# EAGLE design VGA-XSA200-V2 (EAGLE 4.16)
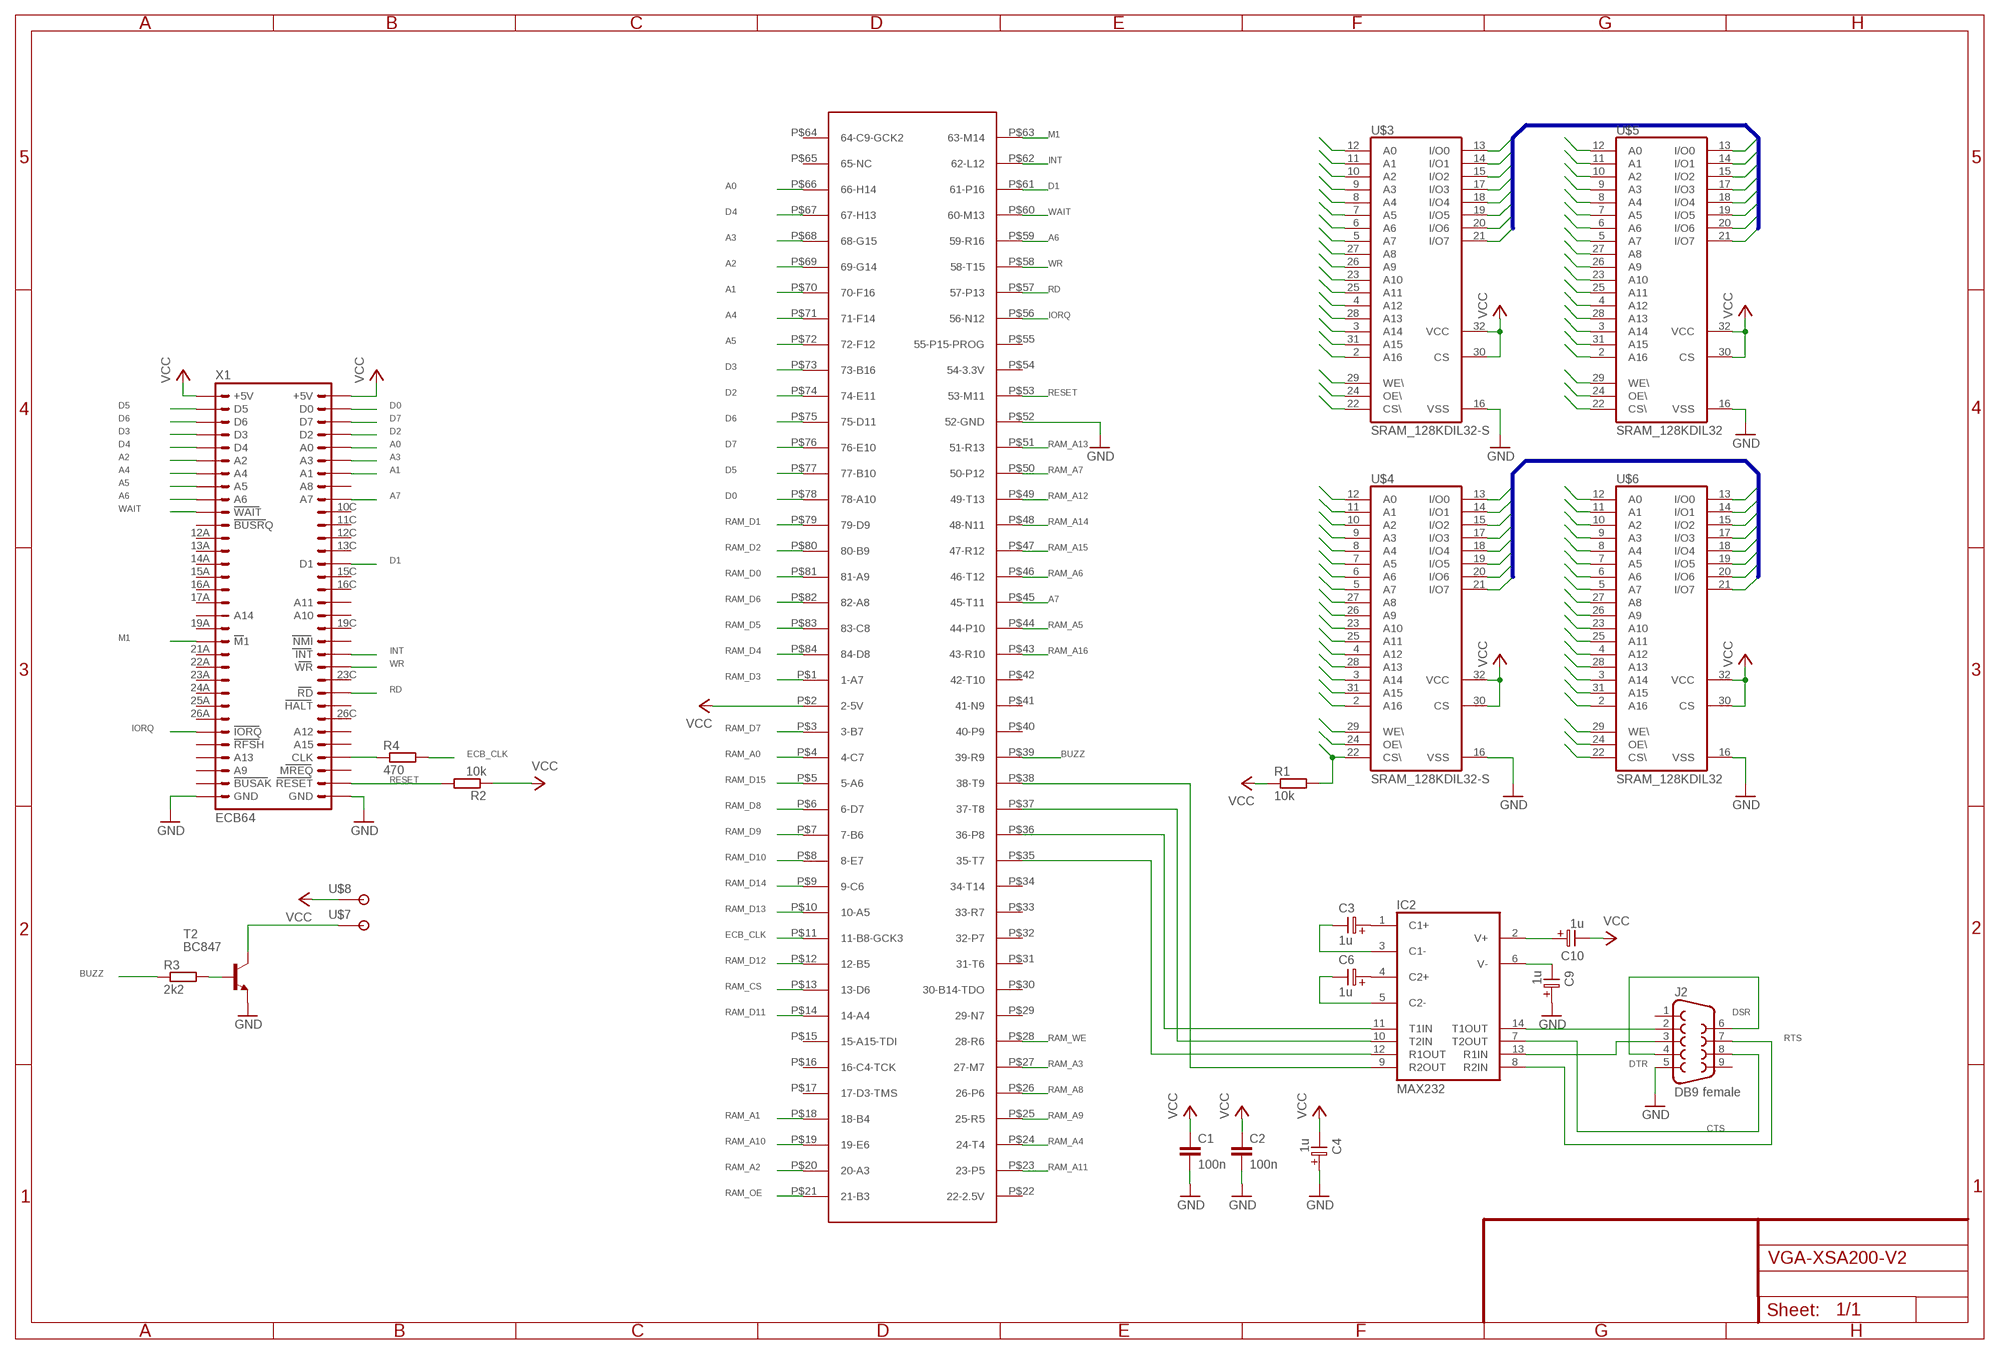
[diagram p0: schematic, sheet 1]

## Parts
C1  100n  C-EU025-025X050  [C025-025X050]
C2  100n  C-EU025-025X050  [C025-025X050]
C3  1u  ELC-2,5L  [ES-2,5L]
C4  1u  ELC-2,5L  [ES-2,5L]
C6  1u  ELC-2,5L  [ES-2,5L]
C9  1u  ELC-2,5L  [ES-2,5L]
C10  1u  ELC-2,5L  [ES-2,5L]
IC2  MAX232  [DIL16]
J2  DB9 female  F09H  [F09H]
R1  10k  R-EU_M1206  [M1206]
R2  10k  R-EU_M1206  [M1206]
R3  2k2  R-EU_M1206  [M1206]
R4  470  R-EU_0204/7  [0204/7]
T2  BC847  BC847-NPN-SOT23-BEC  [SOT23-BEC]
U$1  XSA-200  [XSA-200]
U$3  SRAM_128KDIL32-S  [DIL32-2.PAC]
U$4  SRAM_128KDIL32-S  [DIL32-2.PAC]
U$5  SRAM_128KDIL32  [DIL32]
U$6  SRAM_128KDIL32  [DIL32]
U$7  SPAREPAD10L  [PAD_10_LONG]
U$8  SPAREPAD10L  [PAD_10_LONG]
X1  ECB64  [ML64ECB]

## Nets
A0: U$1.P$66(66-H14) X1.A0
A1: U$1.P$70(70-F16) X1.A1
A2: U$1.P$69(69-G14) X1.A2
A3: U$1.P$68(68-G15) X1.A3
A4: U$1.P$71(71-F14) X1.A4
A5: U$1.P$72(72-F12) X1.A5
A6: U$1.P$59(59-R16) X1.A6
A7: U$1.P$45(45-T11) X1.A7
BUZZ: R3.1 U$1.P$39(39-R9)
CTS: IC2.7(T2OUT) J2.8
D0: U$1.P$78(78-A10) X1.D0
D1: U$1.P$61(61-P16) X1.D1
D2: U$1.P$74(74-E11) X1.D2
D3: U$1.P$73(73-B16) X1.D3
D4: U$1.P$67(67-H13) X1.D4
D5: U$1.P$77(77-B10) X1.D5
D6: U$1.P$75(75-D11) X1.D6
D7: U$1.P$76(76-E10) X1.D7
ECB_CLK: R4.2 U$1.P$11(11-B8-GCK3)
GND: C1.2 C2.2 C4.1 C9.1 J2.5 T2.E U$1.P$52(52-GND) U$3.16(VSS) U$4.16(VSS) U$5.16(VSS) U$6.16(VSS) X1.GND X1.GND@1(GND)
INT: U$1.P$62(62-L12) X1.INT
IORQ: U$1.P$56(56-N12) X1.IORQ
M1: U$1.P$63(63-M14) X1.M1
N$1: IC2.11(T1IN) U$1.P$36(36-P8)
N$2: IC2.12(R1OUT) U$1.P$35(35-T7)
N$3: C3.1 IC2.1(C1+)
N$4: IC2.10(T2IN) U$1.P$37(37-T8)
N$5: C6.1 IC2.4(C2+)
N$6: C3.2 IC2.3(C1-)
N$7: C6.2 IC2.5(C2-)
N$8: IC2.9(R2OUT) U$1.P$38(38-T9)
N$9: T2.C U$7.P$1
N$10: C9.2 IC2.6(V-)
N$11: R3.2 T2.B
N$12: R4.1 X1.CLK
N$13: C10.1 IC2.2(V+)
N$24: J2.4 J2.6
RAM_A0: U$1.P$4(4-C7) U$3.12(A0) U$4.12(A0) U$5.12(A0) U$6.12(A0)
RAM_A1: U$1.P$18(18-B4) U$3.11(A1) U$4.11(A1) U$5.11(A1) U$6.11(A1)
RAM_A2: U$1.P$20(20-A3) U$3.10(A2) U$4.10(A2) U$5.10(A2) U$6.10(A2)
RAM_A3: U$1.P$27(27-M7) U$3.9(A3) U$4.9(A3) U$5.9(A3) U$6.9(A3)
RAM_A4: U$1.P$24(24-T4) U$3.8(A4) U$4.8(A4) U$5.8(A4) U$6.8(A4)
RAM_A5: U$1.P$44(44-P10) U$3.7(A5) U$4.7(A5) U$5.7(A5) U$6.7(A5)
RAM_A6: U$1.P$46(46-T12) U$3.6(A6) U$4.6(A6) U$5.6(A6) U$6.6(A6)
RAM_A7: U$1.P$50(50-P12) U$3.5(A7) U$4.5(A7) U$5.5(A7) U$6.5(A7)
RAM_A8: U$1.P$26(26-P6) U$3.27(A8) U$4.27(A8) U$5.27(A8) U$6.27(A8)
RAM_A9: U$1.P$25(25-R5) U$3.26(A9) U$4.26(A9) U$5.26(A9) U$6.26(A9)
RAM_A10: U$1.P$19(19-E6) U$3.23(A10) U$4.23(A10) U$5.23(A10) U$6.23(A10)
RAM_A11: U$1.P$23(23-P5) U$3.25(A11) U$4.25(A11) U$5.25(A11) U$6.25(A11)
RAM_A12: U$1.P$49(49-T13) U$3.4(A12) U$4.4(A12) U$5.4(A12) U$6.4(A12)
RAM_A13: U$1.P$51(51-R13) U$3.28(A13) U$4.28(A13) U$5.28(A13) U$6.28(A13)
RAM_A14: U$1.P$48(48-N11) U$3.3(A14) U$4.3(A14) U$5.3(A14) U$6.3(A14)
RAM_A15: U$1.P$47(47-R12) U$3.31(A15) U$4.31(A15) U$5.31(A15) U$6.31(A15)
RAM_A16: U$1.P$43(43-R10) U$3.2(A16) U$4.2(A16) U$5.2(A16) U$6.2(A16)
RAM_CS: R1.2 U$1.P$13(13-D6) U$3.22(CS\) U$4.22(CS\) U$5.22(CS\) U$6.22(CS\)
RAM_D0: U$1.P$81(81-A9) U$4.13(I/O0) U$6.13(I/O0)
RAM_D1: U$1.P$79(79-D9) U$4.14(I/O1) U$6.14(I/O1)
RAM_D2: U$1.P$80(80-B9) U$4.15(I/O2) U$6.15(I/O2)
RAM_D3: U$1.P$1(1-A7) U$4.17(I/O3) U$6.17(I/O3)
RAM_D4: U$1.P$84(84-D8) U$4.18(I/O4) U$6.18(I/O4)
RAM_D5: U$1.P$83(83-C8) U$4.19(I/O5) U$6.19(I/O5)
RAM_D6: U$1.P$82(82-A8) U$4.20(I/O6) U$6.20(I/O6)
RAM_D7: U$1.P$3(3-B7) U$4.21(I/O7) U$6.21(I/O7)
RAM_D8: U$1.P$6(6-D7) U$3.13(I/O0) U$5.13(I/O0)
RAM_D9: U$1.P$7(7-B6) U$3.14(I/O1) U$5.14(I/O1)
RAM_D10: U$1.P$8(8-E7) U$3.15(I/O2) U$5.15(I/O2)
RAM_D11: U$1.P$14(14-A4) U$3.17(I/O3) U$5.17(I/O3)
RAM_D12: U$1.P$12(12-B5) U$3.18(I/O4) U$5.18(I/O4)
RAM_D13: U$1.P$10(10-A5) U$3.19(I/O5) U$5.19(I/O5)
RAM_D14: U$1.P$9(9-C6) U$3.20(I/O6) U$5.20(I/O6)
RAM_D15: U$1.P$5(5-A6) U$3.21(I/O7) U$5.21(I/O7)
RAM_OE: U$1.P$21(21-B3) U$3.24(OE\) U$4.24(OE\) U$5.24(OE\) U$6.24(OE\)
RAM_WE: U$1.P$28(28-R6) U$3.29(WE\) U$4.29(WE\) U$5.29(WE\) U$6.29(WE\)
RD: U$1.P$57(57-P13) X1.RD
RESET: R2.2 U$1.P$53(53-M11) X1.RESET
RTS: IC2.8(R2IN) J2.7
RXD: IC2.13(R1IN) J2.3
TXD: IC2.14(T1OUT) J2.2
VCC: C1.1 C2.1 C4.2 C10.2 R1.1 R2.1 U$1.P$2(2-5V) U$3.30(CS) U$3.32(VCC) U$4.30(CS) U$4.32(VCC) U$5.30(CS) U$5.32(VCC) U$6.30(CS) U$6.32(VCC) U$8.P$1 X1.+5V X1.+5V@1(+5V)
WAIT: U$1.P$60(60-M13) X1.WAIT
WR: U$1.P$58(58-T15) X1.WR
Unconnected: J2.1 J2.9 U$1.P$15(15-A15-TDI) U$1.P$16(16-C4-TCK) U$1.P$17(17-D3-TMS) U$1.P$22(22-2.5V) U$1.P$29(29-N7) U$1.P$30(30-B14-TDO) U$1.P$31(31-T6) U$1.P$32(32-P7) U$1.P$33(33-R7) U$1.P$34(34-T14) U$1.P$40(40-P9) U$1.P$41(41-N9) U$1.P$42(42-T10) U$1.P$54(54-3.3V) U$1.P$55(55-P15-PROG) U$1.P$64(64-C9-GCK2) U$1.P$65(65-NC) X1.10C X1.11C X1.12A X1.12C X1.13A X1.13C X1.14A X1.15A X1.15C X1.16A X1.16C X1.17A X1.19A X1.19C X1.21A X1.22A X1.23A X1.23C X1.24A X1.25A X1.26A X1.26C X1.A8 X1.A9 X1.A10 X1.A11 X1.A12 X1.A13 X1.A14 X1.A15 X1.BUSAK X1.BUSRQ X1.HALT X1.MREQ X1.NMI X1.RFSH

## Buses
B$1
B$2

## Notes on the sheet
- DSR
- DTR

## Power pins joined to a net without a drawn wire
GND: IC2.15(GND)
VCC: IC2.16(VCC)

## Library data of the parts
C1 C2 = rcl:C-EU: CAPACITOR, European symbol
C3 C4 C6 C9 C10 = discrete:ELC-2,5L
IC2 = maxim:MAX232: RS232 TRANSEIVER
J2 = con-subd:F09: SUB-D
R1-R4 = rcl:R-EU_: RESISTOR, European symbol
T2 = transistor:*-NPN-: NPN Transistror
U$1 = xess:XSA-200
U$3-U$6 = AD_SRAM:SRAM_128K
U$7 U$8 = ad:SPAREPAD
X1 = con-vg:ECB64: CONNECTOR male, 64 pins, block, type C, rows AC, grid 5.08 mm

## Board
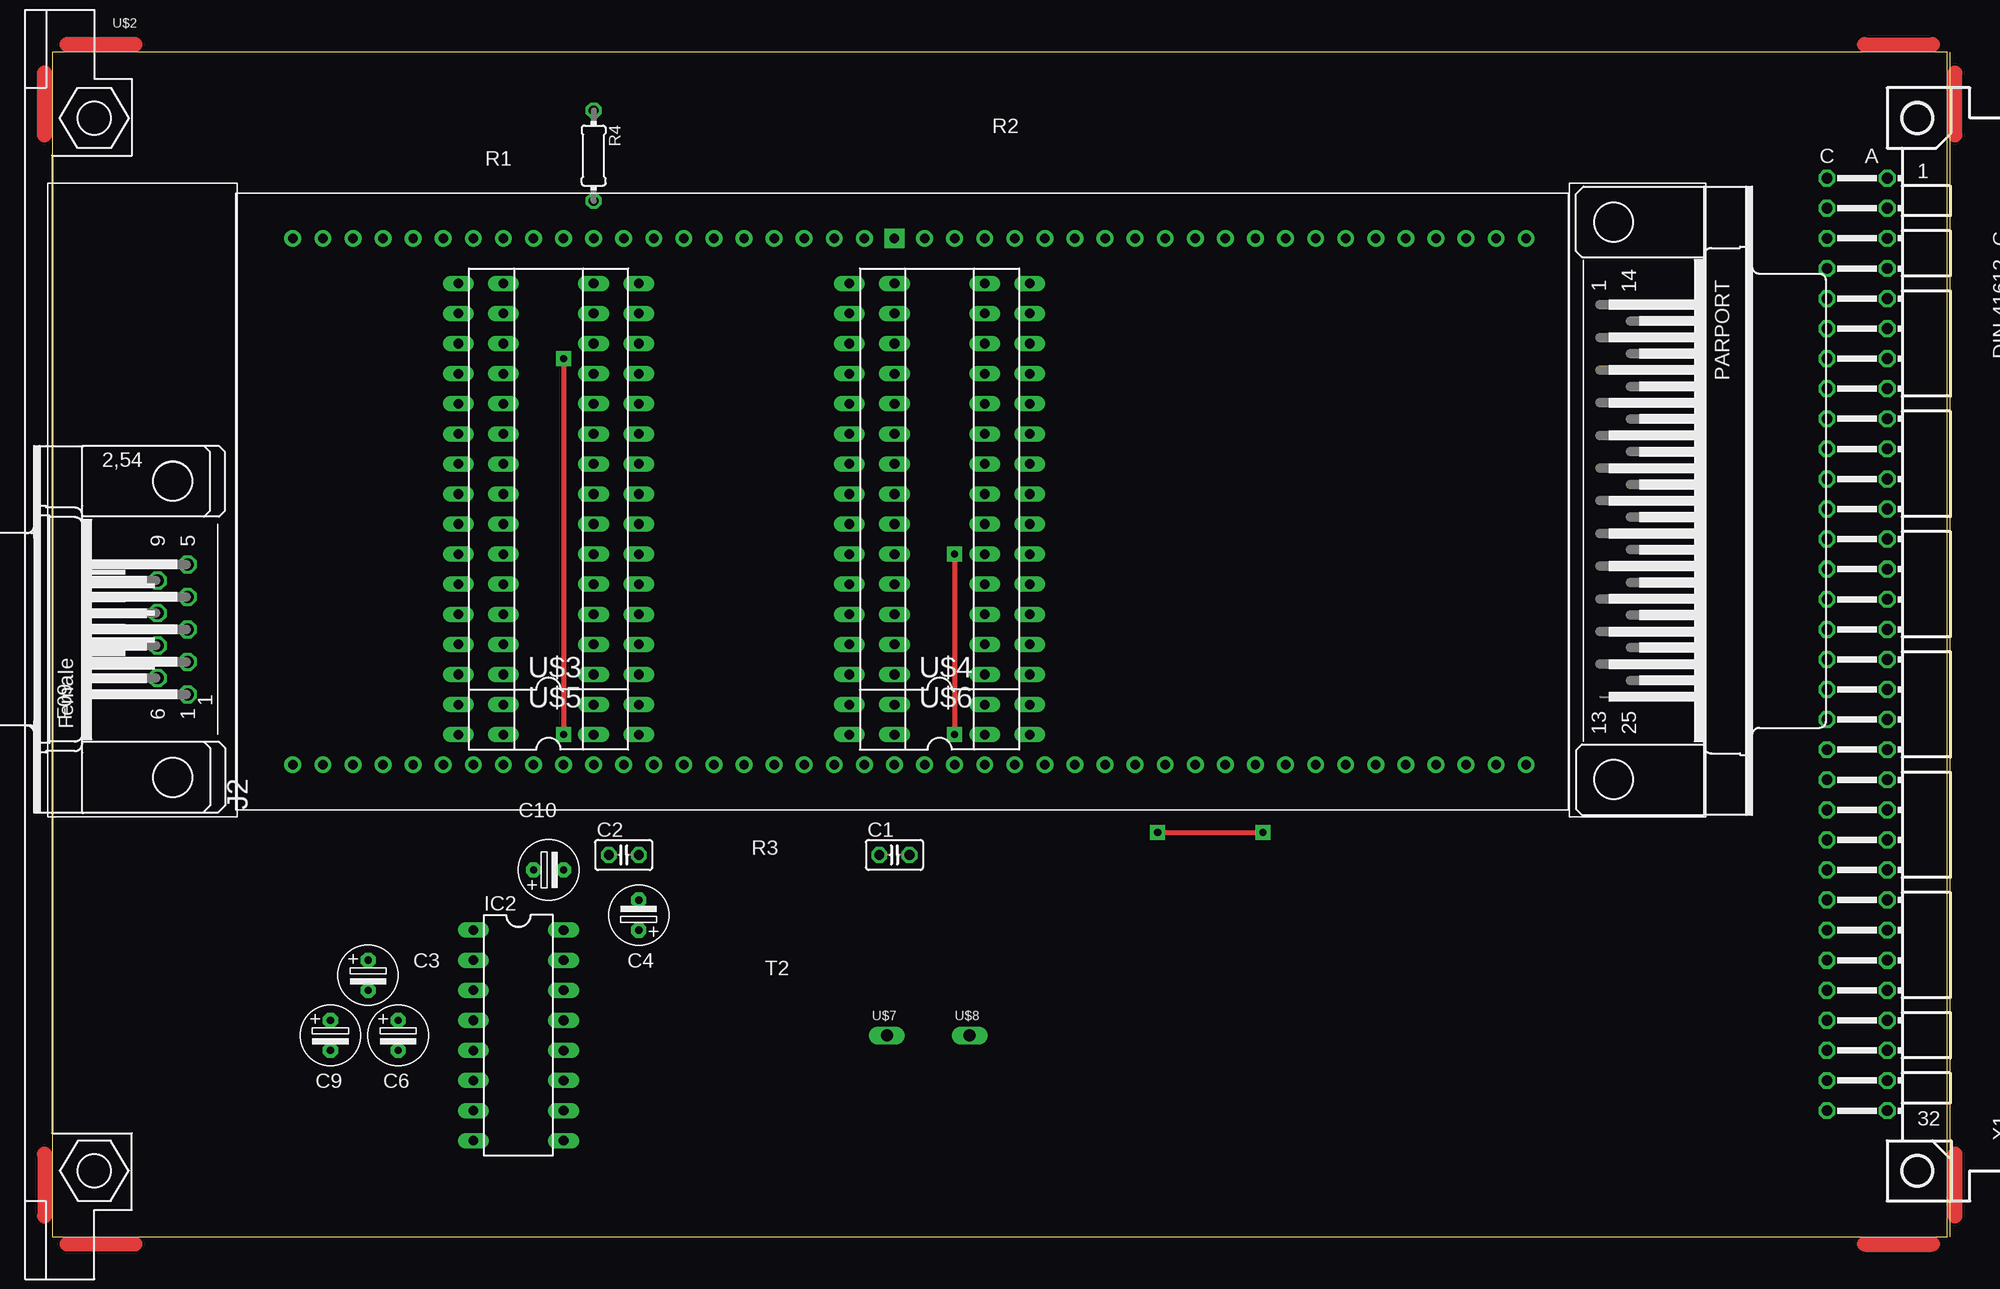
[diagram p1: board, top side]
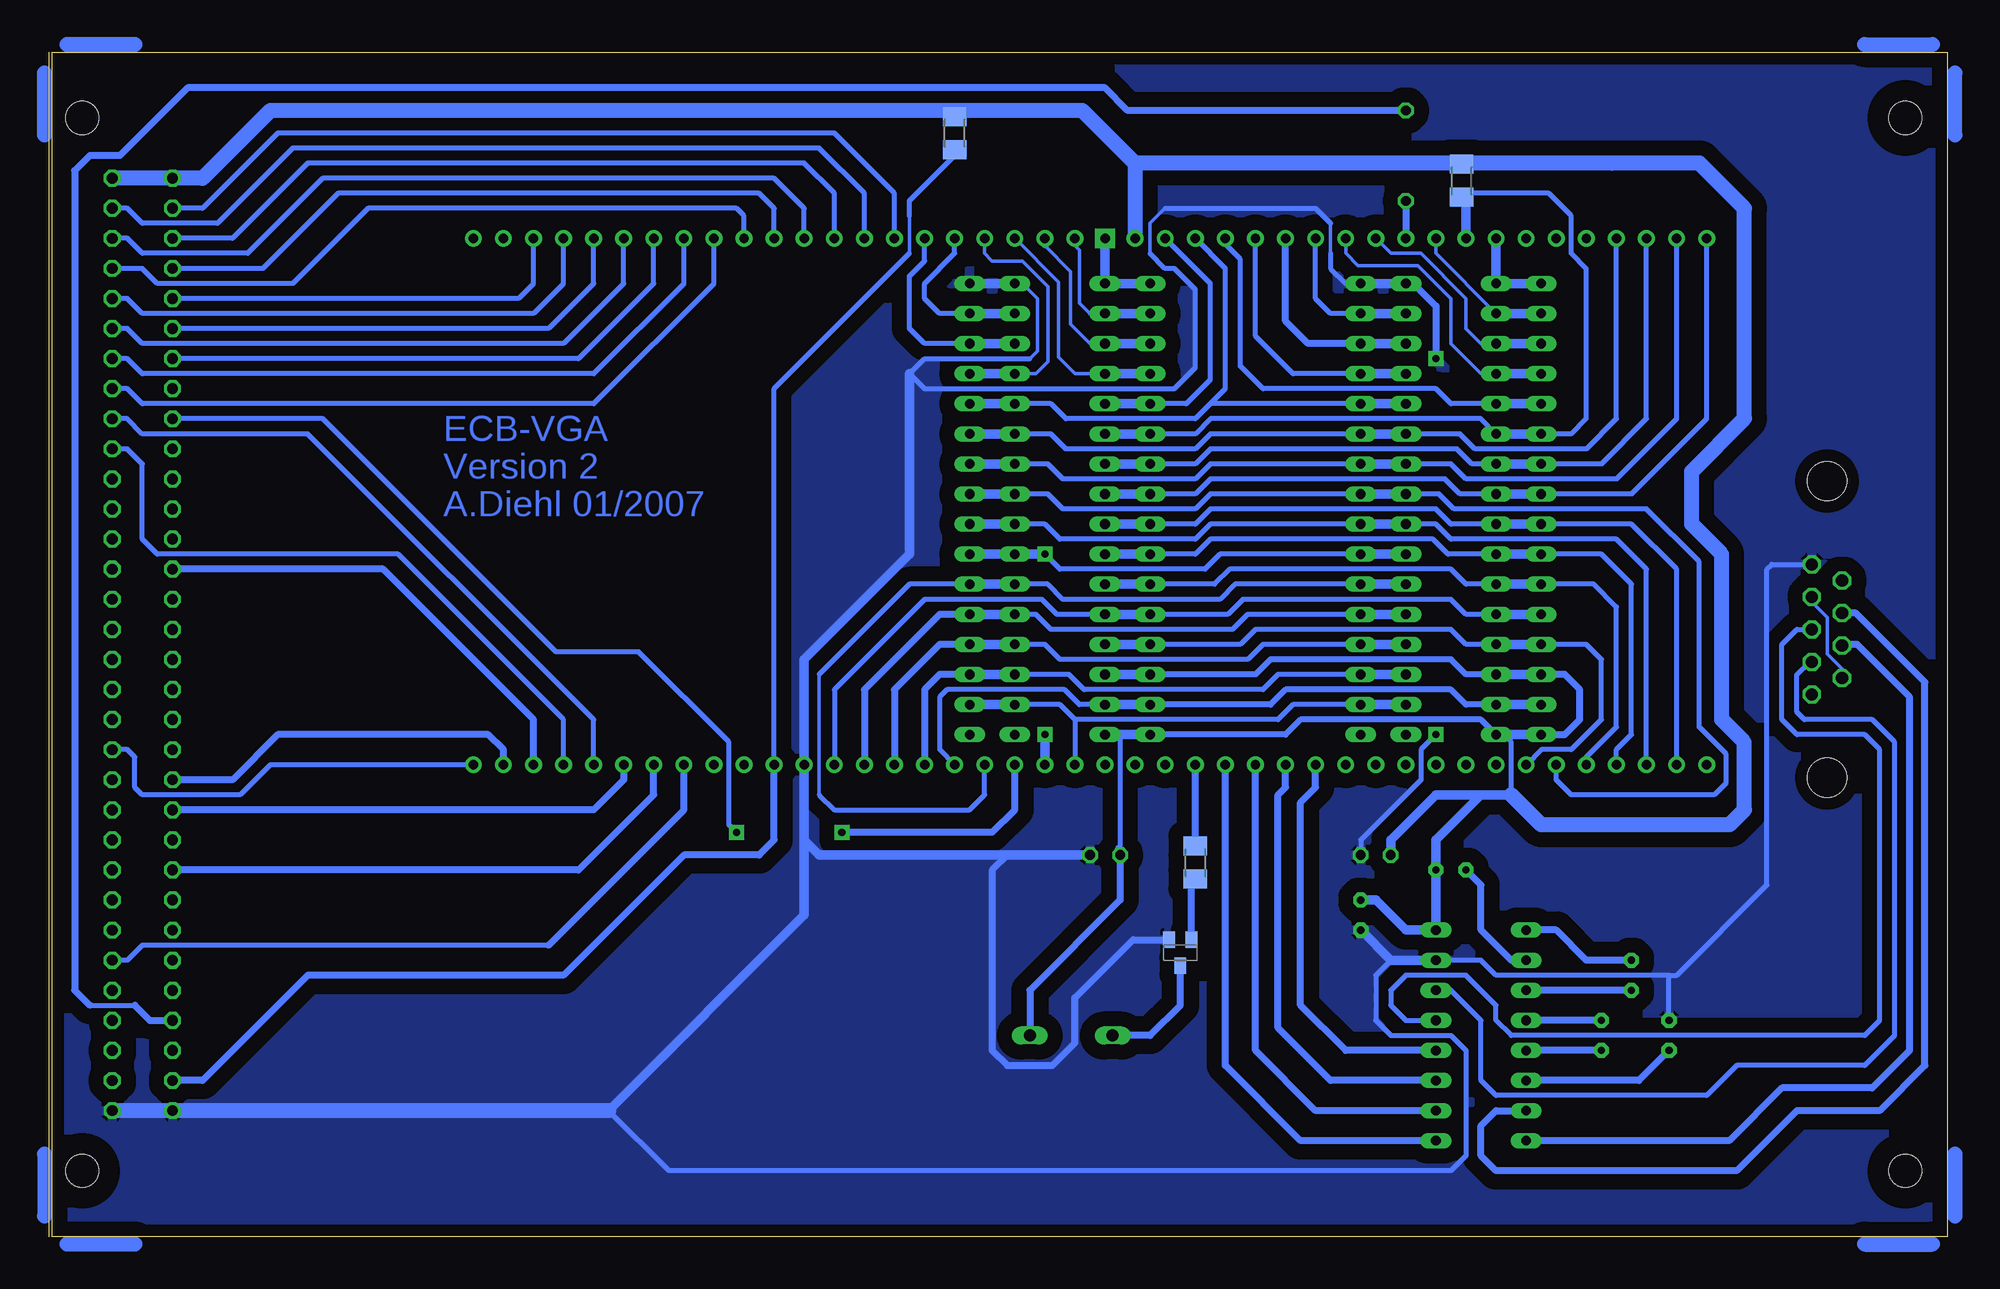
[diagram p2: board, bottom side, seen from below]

Size 160.27 x 100.03 mm. Coordinates in mm from the lower left corner, seen from the top.
Copper layers (1*16): Top 0.035mm / dielectric 1.5mm / Bottom 0.035mm
Design rules "default": minimum track width 10mil, minimum drill 24mil, track to track 50mil, track to pad 60mil, pad to pad 50mil, via to via 50mil, smd to smd 40mil, copper to edge 40mil, drill to drill 8mil, minimum pad ring 10mil, minimum via ring 8mil, stop-mask expansion 4mil, vias tented up to drill 0mil, thermal gap 10mil

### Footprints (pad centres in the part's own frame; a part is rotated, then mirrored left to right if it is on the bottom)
C025-025X050 = drill 0.813 octagon: 1 -1.27,0; 2 1.27,0
ES-2,5L = drill 0.61 pad 1.27 octagon: 1 0,0; 2 2.54,0
DIL16 = drill 0.813 long: 1 -8.89,-3.81; 2 -6.35,-3.81; 3 -3.81,-3.81; 4 -1.27,-3.81; 5 1.27,-3.81; 6 3.81,-3.81; 7 6.35,-3.81; 8 8.89,-3.81; 9 8.89,3.81; 10 6.35,3.81; 11 3.81,3.81; 12 1.27,3.81; 13 -1.27,3.81; 14 -3.81,3.81; 15 -6.35,3.81; 16 -8.89,3.81
F09H = drill 1.016 octagon: 1 -5.486,-1.27; 2 -2.743,-1.27; 3 0,-1.27; 4 2.743,-1.27; 5 5.486,-1.27; 6 -4.115,1.27; 7 -1.372,1.27; 8 1.372,1.27; 9 4.115,1.27 | hole 3.302: -12.522,0; 12.522,0
M1206 = smd 1.6 x 2: 1 -1.4,0; 2 1.4,0
0204/7 = drill 0.813 octagon: 1 -3.81,0; 2 3.81,0
SOT23-BEC = smd 1 x 1.4: B -0.95,-1.1; C 0,1.1; E 0.95,-1.1
XSA-200 = drill 0.8 pad 1.676 square: P$1 -6.35,0 | drill 0.8 pad 1.422 round: P$2 -6.35,-2.54; P$3 -6.35,-5.08; P$4 -6.35,-7.62; P$5 -6.35,-10.16; P$6 -6.35,-12.7; P$7 -6.35,-15.24; P$8 -6.35,-17.78; P$9 -6.35,-20.32; P$10 -6.35,-22.86; P$11 -6.35,-25.4; P$12 -6.35,-27.94; P$13 -6.35,-30.48; P$14 -6.35,-33.02; P$15 -6.35,-35.56; P$16 -6.35,-38.1; P$17 -6.35,-40.64; P$18 -6.35,-43.18; P$19 -6.35,-45.72; P$20 -6.35,-48.26; P$21 -6.35,-50.8; P$22 38.1,-50.8; P$23 38.1,-48.26; P$24 38.1,-45.72; P$25 38.1,-43.18; P$26 38.1,-40.64; P$27 38.1,-38.1; P$28 38.1,-35.56; P$29 38.1,-33.02; P$30 38.1,-30.48; P$31 38.1,-27.94; P$32 38.1,-25.4; P$33 38.1,-22.86; P$34 38.1,-20.32; P$35 38.1,-17.78; P$36 38.1,-15.24; P$37 38.1,-12.7; P$38 38.1,-10.16; P$39 38.1,-7.62; P$40 38.1,-5.08; P$41 38.1,-2.54; P$42 38.1,0; P$43 38.1,2.54; P$44 38.1,5.08; P$45 38.1,7.62; P$46 38.1,10.16; P$47 38.1,12.7; P$48 38.1,15.24; P$49 38.1,17.78; P$50 38.1,20.32; P$51 38.1,22.86; P$52 38.1,25.4; P$53 38.1,27.94; P$54 38.1,30.48; P$55 38.1,33.02; P$56 38.1,35.56; P$57 38.1,38.1; P$58 38.1,40.64; P$59 38.1,43.18; P$60 38.1,45.72; P$61 38.1,48.26; P$62 38.1,50.8; P$63 38.1,53.34; P$64 -6.35,53.34; P$65 -6.35,50.8; P$66 -6.35,48.26; P$67 -6.35,45.72; P$68 -6.35,43.18; P$69 -6.35,40.64; P$70 -6.35,38.1; P$71 -6.35,35.56; P$72 -6.35,33.02; P$73 -6.35,30.48; P$74 -6.35,27.94; P$75 -6.35,25.4; P$76 -6.35,22.86; P$77 -6.35,20.32; P$78 -6.35,17.78; P$79 -6.35,15.24; P$80 -6.35,12.7; P$81 -6.35,10.16; P$82 -6.35,7.62; P$83 -6.35,5.08; P$84 -6.35,2.54
EK-FP = hole 2.794: 3.556,44.45; 3.556,-44.45
DIL32-2.PAC = drill 0.813 long: 1 -19.05,-3.81; 2 -16.51,-3.81; 3 -13.97,-3.81; 4 -11.43,-3.81; 5 -8.89,-3.81; 6 -6.35,-3.81; 7 -3.81,-3.81; 8 -1.27,-3.81; 9 1.27,-3.81; 10 3.81,-3.81; 11 6.35,-3.81; 12 8.89,-3.81; 13 11.43,-3.81; 14 13.97,-3.81; 15 16.51,-3.81; 16 19.05,-3.81; 17 19.05,3.81; 18 16.51,3.81; 19 13.97,3.81; 20 11.43,3.81; 21 8.89,3.81; 22 6.35,3.81; 23 3.81,3.81; 24 1.27,3.81; 25 -1.27,3.81; 26 -3.81,3.81; 27 -6.35,3.81; 28 -8.89,3.81; 29 -11.43,3.81; 30 -13.97,3.81; 31 -16.51,3.81; 32 -19.05,3.81
DIL32 = drill 0.813 long: 1 -19.05,-7.62; 2 -16.51,-7.62; 3 -13.97,-7.62; 4 -11.43,-7.62; 5 -8.89,-7.62; 6 -6.35,-7.62; 7 -3.81,-7.62; 8 -1.27,-7.62; 9 1.27,-7.62; 10 3.81,-7.62; 11 6.35,-7.62; 12 8.89,-7.62; 13 11.43,-7.62; 14 13.97,-7.62; 15 16.51,-7.62; 16 19.05,-7.62; 17 19.05,7.62; 18 16.51,7.62; 19 13.97,7.62; 20 11.43,7.62; 21 8.89,7.62; 22 6.35,7.62; 23 3.81,7.62; 24 1.27,7.62; 25 -1.27,7.62; 26 -3.81,7.62; 27 -6.35,7.62; 28 -8.89,7.62; 29 -11.43,7.62; 30 -13.97,7.62; 31 -16.51,7.62; 32 -19.05,7.62
PAD_10_LONG = drill 1 long: P$1 0,0
ML64ECB = drill 0.914 octagon: 10C -7.62,16.51; 11C -7.62,13.97; 12A -2.54,11.43; 12C -7.62,11.43; 13A -2.54,8.89; 13C -7.62,8.89; 14A -2.54,6.35; 15A -2.54,3.81; 15C -7.62,3.81; 16A -2.54,1.27; 16C -7.62,1.27; 17A -2.54,-1.27; 19A -2.54,-6.35; 19C -7.62,-6.35; 21A -2.54,-11.43; 22A -2.54,-13.97; 23A -2.54,-16.51; 23C -7.62,-16.51; 24A -2.54,-19.05; 25A -2.54,-21.59; 26A -2.54,-24.13; 26C -7.62,-24.13; +5V -2.54,39.37; +5V@1 -7.62,39.37; A0 -7.62,29.21; A1 -7.62,24.13; A2 -2.54,26.67; A3 -7.62,26.67; A4 -2.54,24.13; A5 -2.54,21.59; A6 -2.54,19.05; A7 -7.62,19.05; A8 -7.62,21.59; A9 -2.54,-34.29; A10 -7.62,-3.81; A11 -7.62,-1.27; A12 -7.62,-26.67; A13 -2.54,-31.75; A14 -2.54,-3.81; A15 -7.62,-29.21; BUSAK -2.54,-36.83; BUSRQ -2.54,13.97; CLK -7.62,-31.75; D0 -7.62,36.83; D1 -7.62,6.35; D2 -7.62,31.75; D3 -2.54,31.75; D4 -2.54,29.21; D5 -2.54,36.83; D6 -2.54,34.29; D7 -7.62,34.29; GND -2.54,-39.37; GND@1 -7.62,-39.37; HALT -7.62,-21.59; INT -7.62,-11.43; IORQ -2.54,-26.67; M1 -2.54,-8.89; MREQ -7.62,-34.29; NMI -7.62,-8.89; RD -7.62,-19.05; RESET -7.62,-36.83; RFSH -2.54,-29.21; WAIT -2.54,16.51; WR -7.62,-13.97 | hole 2.794: 0,44.45; 0,-44.45

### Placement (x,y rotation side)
C1  71.12,32.23 0 top
C2  48.26,32.23 0 top
C3  26.67,23.34 270 top
C4  49.53,25.88 90 top
C6  29.21,18.26 270 top
C9  23.5,18.26 270 top
C10  40.64,30.96 0 top
IC2  39.37,16.99 270 top
J2  10.16,51.28 90 top
R1  41.01,89.17 270 bottom
R2  83.82,93.19 270 bottom
R3  63.5,31.6 270 bottom
R4  45.72,91.29 270 top
T2  64.77,23.98 180 bottom
U$1  71.12,77.95 270 top
U$2  [EK-FP]  0,50.01 0 top
U$3  41.91,61.44 90 top
U$4  74.93,61.44 90 top
U$5  41.91,61.44 90 top
U$6  74.93,61.44 90 top
U$7  70.48,16.99 0 top
U$8  77.47,16.99 0 top
X1  157.48,50.01 0 top

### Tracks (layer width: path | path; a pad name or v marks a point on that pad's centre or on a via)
A0
  Bottom 0.406: X1.A0 120.65,79.22 119.38,80.49 U$1.P$66
A1
  Bottom 0.406: X1.A1 115.57,74.14 109.22,80.49 U$1.P$70
A2
  Bottom 0.406: X1.A2 153.67,76.68 152.4,75.41 116.84,75.41 111.76,80.49 U$1.P$69
A3
  Bottom 0.406: X1.A3 118.11,76.68 114.3,80.49 U$1.P$68
A4
  Bottom 0.406: X1.A4 153.67,74.14 152.4,72.87 114.3,72.87 106.68,80.49 U$1.P$71
A5
  Bottom 0.406: X1.A5 153.67,71.6 152.4,70.33 114.3,70.33 104.14,80.49 U$1.P$72
A6
  Bottom 0.406: X1.A6 153.67,69.06 152.4,67.79 138.43,67.79 114.3,43.66 U$1.P$59
A7  (via drill 0.6 pad 1.27)
  Top 0.406: v93.34,34.14 v102.23,34.14
  Bottom 0.406: v102.23,34.14 102.87,34.77 102.87,41.76 110.49,49.38 117.47,49.38 137.16,69.06 X1.A7
  Bottom 0.61: U$1.P$45 78.74,36.04 80.64,34.14 v93.34,34.14
BUZZ
  Bottom 0.61: R3.1 U$1.P$39
CTS
  Bottom 0.61: IC2.7 38.1,10.64 39.37,9.37 39.37,6.83 38.1,5.56 17.78,5.56 12.7,10.64 5.71,10.64 1.91,14.45 1.91,46.84 7.72,52.65 J2.8
D0
  Bottom 0.406: X1.D0 147.32,86.84 140.97,93.19 93.98,93.19 88.9,88.11 U$1.P$78
D1
  Bottom 0.61: X1.D1 132.08,56.36 119.38,43.66 U$1.P$61
D2
  Bottom 0.406: X1.D2 142.24,81.76 135.89,88.11 100.33,88.11 99.06,86.84 U$1.P$74
D3
  Bottom 0.406: X1.D3 152.4,81.76 151.13,80.49 139.7,80.49 133.35,86.84 102.23,86.84 101.6,86.21 U$1.P$73
D4
  Bottom 0.406: X1.D4 153.67,79.22 152.4,77.95 119.38,77.95 116.84,80.49 U$1.P$67
D5
  Bottom 0.406: X1.D5 153.67,86.84 152.4,85.57 146.05,85.57 139.7,91.92 95.25,91.92 91.44,88.11 U$1.P$77
D6
  Bottom 0.406: X1.D6 153.67,84.3 152.4,83.03 143.51,83.03 137.16,89.38 99.06,89.38 96.52,86.84 U$1.P$75
D7
  Bottom 0.406: X1.D7 144.78,84.3 138.43,90.65 96.52,90.65 93.98,88.11 U$1.P$76
ECB_CLK
  Bottom 0.61: R4.2 U$1.P$11
GND  (via drill 0.6 pad 1.27)
  Top 0.406: v43.18,74.14 v43.18,42.39
  Bottom 0.305: 67.31,83.03 67.31,85.57 66.04,86.84 | 52.07,85.57 52.07,83.03 | 77.47,74.14 76.83,74.78 76.83,79.22 78.11,80.49
  Bottom 0.406: IC2.15 39.37,23.34 38.1,22.07 23.5,22.07 | 23.5,22.07 22.86,22.07 15.24,29.69 15.24,56.36 14.83,56.77 J2.5 | C9.1 23.5,22.07 | 46.99,23.34 48.26,22.07 48.26,18.26 46.99,16.99 41.91,16.99 40.64,15.72 40.64,6.83 41.91,5.56 107.95,5.56 113.03,10.64 | C2.2 49.53,33.5 44.45,38.58 44.45,41.12 v43.18,42.39 | 67.31,83.03 66.04,81.76 65.28,81.76 63.5,79.98 63.5,73.38 65.28,71.6 86.36,71.6 87.63,72.87 86.36,74.14 77.47,74.14 | 66.04,86.84 53.34,86.84 52.07,85.57 | 52.07,83.03 52.07,81.76 50.8,80.49 U$5.16 | 78.11,80.49 U$4.16
  Bottom 0.61: T2.E 68.75,25.08 73.66,20.17 73.66,16.36 75.56,14.45 79.38,14.45 80.64,15.72 80.64,30.96 79.38,32.23 | U$3.16 45.09,80.49 43.18,78.59 v43.18,74.14
  Bottom 0.813: U$5.16 U$3.16 | U$4.16 U$6.16 | 96.52,33.5 96.52,27.15 113.03,10.64 | 96.52,33.5 U$1.P$52 96.52,48.74 87.63,57.63 87.63,72.87 | IC2.15 46.99,23.34 C4.1 | C1.2 79.38,32.23 95.25,32.23 96.52,33.5
  Bottom 1.27: 113.03,10.64 X1.GND@1 X1.GND
  pour Bottom: 161.93,-2.69 -4.45,-2.69 -4.45,103.35 161.93,103.35
INT
  Bottom 0.61: X1.INT 144.78,38.58 140.97,42.39 123.19,42.39 121.92,41.12 U$1.P$62
IORQ
  Bottom 0.406: X1.IORQ 153.67,23.34 152.4,24.61 118.11,24.61
  Bottom 0.61: 118.11,24.61 106.68,36.04 U$1.P$56
M1
  Bottom 0.406: U$1.P$63 141.6,39.85 144.15,37.31 152.4,37.31 153.03,37.95 153.03,40.49 153.67,41.12 X1.M1
N$1
  Bottom 0.61: IC2.11 52.07,13.18 56.52,17.63 56.52,37.31 55.88,37.95 U$1.P$36
N$2
  Bottom 0.61: IC2.12 50.8,15.72 54.61,19.53 54.61,36.68 53.34,37.95 U$1.P$35
N$3
  Bottom 0.61: C3.1 30.48,23.34 33.02,25.88 IC2.1
N$4
  Bottom 0.61: IC2.10 53.34,10.64 58.42,15.72 U$1.P$37
N$5
  Bottom 0.61: C6.1 IC2.4
N$6
  Bottom 0.61: C3.2 IC2.3
N$7
  Bottom 0.61: C6.2 IC2.5
N$8
  Bottom 0.61: IC2.9 54.61,8.1 60.96,14.45 U$1.P$38
N$9
  Bottom 0.61: U$7.P$1 67.31,16.99 64.77,19.53 T2.C
N$10
  Bottom 0.61: C9.2 26.04,13.18 IC2.6
N$11
  Bottom 0.406: R3.2 63.5,30.33 63.82,30.01
  Bottom 0.61: T2.B 63.82,30.01
N$12
  Bottom 0.406: 156.84,19.53 153.03,19.53
  Bottom 0.61: R4.1 69.22,95.1 71.12,97 148.59,97 154.31,91.29 156.84,91.29 158.12,90.02 158.12,20.8 156.84,19.53 | 153.03,19.53 151.76,18.26 X1.CLK
N$13
  Bottom 0.61: IC2.2 36.83,23.34 39.37,25.88 39.37,29.69 C10.1
N$24
  Bottom 0.305: J2.6 8.89,47.94 10.13,49.18 10.13,52.27 11.43,53.57 J2.4
RAM_A0
  Bottom 0.406: U$5.12 62.23,70.33 | 62.23,70.33 63.5,69.06 74.42,69.06 75.69,70.33 U$4.12 | U$1.P$4 60.96,81.76 60.96,71.6 62.23,70.33
  Bottom 0.813: U$3.12 U$5.12 | U$4.12 U$6.12
RAM_A1
  Bottom 0.406: U$4.11 75.69,67.79 74.42,66.52 63.5,66.52 62.23,67.79 U$5.11 | U$3.11 41.15,67.79 39.88,66.52 30.48,66.52 27.94,69.06 U$1.P$18
  Bottom 0.813: U$3.11 U$5.11 | U$4.11 U$6.11
RAM_A2
  Bottom 0.406: U$5.10 62.23,65.25 63.5,63.98 74.68,63.98 75.95,65.25 U$4.10 | U$1.P$20 22.86,69.06 27.94,63.98 40.64,63.98 41.91,65.25 U$3.10
  Bottom 0.813: U$3.10 U$5.10 | U$4.10 U$6.10
RAM_A3
  Bottom 0.406: U$5.9 62.23,62.71 63.5,61.44 74.68,61.44 75.95,62.71 U$4.9 | U$3.9 42.93,62.71 41.66,61.44 25.4,61.44 20.95,57 20.95,43.03 18.67,40.74 18.67,38.33 19.68,37.31 31.75,37.31 33.02,38.58 U$1.P$27
  Bottom 0.813: U$3.9 U$5.9 | U$4.9 U$6.9
RAM_A4
  Bottom 0.406: U$4.8 76.2,60.17 74.93,58.9 63.5,58.9 62.23,60.17 U$5.8 | U$3.8 43.18,60.17 41.91,58.9 27.94,58.9 25.4,56.36 U$1.P$24
  Bottom 0.813: U$4.8 U$6.8 | U$3.8 U$5.8
RAM_A5  (via drill 0.6 pad 1.27)
  Top 0.406: v76.2,57.63 v76.2,42.39
  Bottom 0.406: U$5.7 61.41,57.63 62.68,56.36 74.93,56.36 v76.2,57.63
  Bottom 0.813: U$3.7 U$5.7 | U$6.7 U$4.7 v76.2,57.63 | v76.2,42.39 U$1.P$44
RAM_A6
  Bottom 0.305: 95.25,47.47 95.25,37.31
  Bottom 0.406: U$5.6 60.16,55.09 61.43,53.82 74.68,53.82 75.95,55.09 U$4.6 | U$6.6 87.63,55.09 95.25,47.47 | 95.25,37.31 93.98,36.04 82.55,36.04 81.28,37.31 U$1.P$46
  Bottom 0.813: U$3.6 U$5.6 | U$4.6 U$6.6
RAM_A7
  Bottom 0.406: U$4.5 76.96,52.55 75.69,51.28 60.35,51.28 59.08,52.55 U$5.5
  Bottom 0.61: U$6.5 85.09,52.55 91.44,46.2 U$1.P$50
  Bottom 0.813: U$4.5 U$6.5 | U$3.5 U$5.5
RAM_A8
  Bottom 0.406: U$3.27 40.64,55.09 41.91,56.36 60.59,56.36 61.86,55.09 U$6.27 | U$1.P$26 30.48,40.49 27.94,43.03 27.94,53.19 29.84,55.09 U$5.27
  Bottom 0.813: U$5.27 U$3.27 | U$6.27 U$4.27
RAM_A9
  Bottom 0.406: U$3.26 42.16,57.63 43.43,58.9 62.23,58.9 63.5,57.63 U$6.26 | U$1.P$25 27.94,41.12 26.67,42.39 26.67,55.09 29.21,57.63 U$5.26
  Bottom 0.813: U$5.26 U$3.26 | U$6.26 U$4.26
RAM_A10
  Bottom 0.406: U$6.23 63.5,65.25 62.23,66.52 41.4,66.52 40.13,65.25 U$3.23 | U$1.P$19 25.4,69.06 29.21,65.25 U$5.23
  Bottom 0.813: U$6.23 U$4.23 | U$5.23 U$3.23
RAM_A11
  Bottom 0.406: U$3.25 41.91,60.17 43.18,61.44 62.23,61.44 63.5,60.17 U$6.25 | U$1.P$23 22.86,56.36 26.67,60.17 U$5.25
  Bottom 0.813: U$5.25 U$3.25 | U$6.25 U$4.25
RAM_A12
  Bottom 0.406: U$5.4 57.78,50.01 59.05,48.74 74.93,48.74 76.2,50.01 U$4.4
  Bottom 0.61: U$6.4 85.09,50.01 88.9,46.2 U$1.P$49
  Bottom 0.813: U$3.4 U$5.4 | U$4.4 U$6.4
RAM_A13
  Bottom 0.406: U$3.28 40.64,52.55 41.91,53.82 59.49,53.82 60.76,52.55 U$6.28 | U$4.28 75.18,52.55 76.45,53.82 86.36,53.82 93.98,46.2 U$1.P$51
  Bottom 0.813: U$5.28 U$3.28 | U$6.28 U$4.28
RAM_A14
  Bottom 0.406: U$5.3 56.52,47.47 57.78,46.2 72.9,46.2 74.17,47.47 U$4.3
  Bottom 0.61: U$6.3 85.09,47.47 86.36,46.2 U$1.P$48
  Bottom 0.813: U$3.3 U$5.3 | U$4.3 U$6.3
RAM_A15
  Bottom 0.406: U$4.31 73.29,44.93 74.56,46.2 84.45,46.2 85.09,45.57 85.09,41.12 U$1.P$47
  Bottom 0.508: U$6.31 57.15,44.93 55.88,46.2 41.91,46.2 40.64,44.93 U$3.31
  Bottom 0.813: U$6.31 U$4.31 | U$5.31 U$3.31
RAM_A16
  Bottom 0.406: U$4.2 74.93,44.93 73.66,43.66 | 73.66,43.66 56.52,43.66 55.24,44.93 U$5.2 | 73.66,43.66 U$1.P$43
  Bottom 0.813: U$4.2 U$6.2 | U$3.2 U$5.2
RAM_CS
  Bottom 0.406: U$3.22 39.37,69.06 62.23,69.06 63.5,67.79 U$6.22 | U$5.22 31.75,67.79 30.48,69.06 30.48,81.76 31.75,83.03 31.75,86.21 33.66,88.11 41.27,88.11 41.01,87.85 R1.2 40.98,87.77 40.64,88.11
  Bottom 0.813: U$5.22 U$3.22 | U$6.22 U$4.22 | 40.64,88.11 U$1.P$13
RAM_D0
  Bottom 0.305: U$1.P$81 81.28,83.03 80.64,82.4 78.11,82.4 75.95,80.24 75.95,73.89 76.96,72.87 U$4.13
  Bottom 0.813: U$4.13 U$6.13
RAM_D1
  Bottom 0.406: U$6.14 86.36,75.41 87.63,76.68 87.63,81.13 86.36,82.4 U$1.P$79
  Bottom 0.813: U$4.14 U$6.14
RAM_D2
  Bottom 0.406: U$6.15 85.09,77.95 86.36,79.22 86.36,80.49 83.82,83.03 U$1.P$80
  Bottom 0.813: U$4.15 U$6.15
RAM_D3
  Bottom 0.813: U$6.17 U$4.17 71.12,81.76 U$1.P$1
RAM_D4
  Bottom 0.305: U$1.P$84 73.66,83.67 73.28,83.29 73.28,78.84 72.39,77.95
  Bottom 0.406: U$4.18 72.39,77.95
  Bottom 0.813: U$6.18 U$4.18
RAM_D5
  Bottom 0.305: U$4.19 72.39,75.41 74.04,77.06 74.04,81.51 76.2,83.67
  Bottom 0.406: 76.2,83.67 U$1.P$83
  Bottom 0.813: U$6.19 U$4.19
RAM_D6
  Bottom 0.305: U$1.P$82 75.06,80.62 75.06,74.27 73.66,72.87 U$4.20
  Bottom 0.813: U$6.20 U$4.20
RAM_D7
  Bottom 0.406: U$1.P$3 62.23,80.49 62.23,72.36 64.26,70.33 U$6.21
  Bottom 0.813: U$6.21 U$4.21
RAM_D8
  Bottom 0.406: U$5.13 55.24,72.87 58.42,76.05 U$1.P$6
  Bottom 0.813: U$3.13 U$5.13
RAM_D9
  Bottom 0.61: U$5.14 53.98,75.41 55.88,77.32 U$1.P$7
  Bottom 0.813: U$3.14 U$5.14
RAM_D10
  Bottom 0.406: U$5.15 52.07,77.95 53.34,79.22 U$1.P$8
  Bottom 0.813: U$3.15 U$5.15
RAM_D11
  Bottom 0.813: U$5.17 U$3.17 38.1,81.76 U$1.P$14
RAM_D12
  Bottom 0.305: U$3.18 43.18,83.03 U$1.P$12
  Bottom 0.813: U$5.18 U$3.18
RAM_D13
  Bottom 0.305: U$1.P$10 46.99,83.03 44.45,83.03 40.64,79.22 40.64,76.68 39.37,75.41 U$3.19
  Bottom 0.813: U$5.19 U$3.19
RAM_D14
  Bottom 0.305: U$3.20 39.37,72.87 41.91,75.41 41.91,79.22 44.7,82.02 49.78,82.02 50.8,83.03 U$1.P$9
  Bottom 0.813: U$5.20 U$3.20
RAM_D15
  Bottom 0.406: U$3.21 41.91,70.33 43.18,71.6 57.78,71.6 59.69,73.51 59.69,82.52 60.96,83.79 U$1.P$5
  Bottom 0.813: U$5.21 U$3.21
RAM_OE
  Bottom 0.406: U$3.24 41.15,62.71 42.42,63.98 62.23,63.98 63.5,62.71 U$6.24 | U$5.24 26.67,62.71 20.32,69.06 U$1.P$21
  Bottom 0.813: U$5.24 U$3.24 | U$6.24 U$4.24
RAM_WE
  Bottom 0.406: U$3.29 40.64,50.01 41.91,51.28 58.42,51.28 59.69,50.01 U$6.29 | U$1.P$28 34.29,41.12 31.75,41.12 29.21,43.66 29.21,48.74 30.48,50.01 U$5.29
  Bottom 0.813: U$5.29 U$3.29 | U$6.29 U$4.29
RD
  Bottom 0.61: X1.RD 115.57,30.96 109.22,37.31 U$1.P$57
RESET
  Bottom 0.305: 87.63,83.03 87.63,86.21
  Bottom 0.406: R2.2 83.82,91.29 87.63,87.48 87.63,86.21 | 87.63,83.03 99.06,71.6 U$1.P$53
  Bottom 0.61: X1.RESET 147.32,13.18 138.43,22.07 116.84,22.07 106.68,32.23 100.33,32.23 99.06,33.5 U$1.P$53
RTS
  Bottom 0.61: IC2.8 18.41,8.1 13.97,12.55 6.35,12.55 3.17,15.72 3.17,45.57 7.62,50.01 8.89,50.01 J2.7
RXD
  Bottom 0.406: IC2.13 45.72,18.26 46.99,19.53 46.99,20.8 45.72,22.07 40.64,22.07 38.1,19.53 38.1,18.26 36.83,16.99 6.99,16.99 5.71,18.26 5.71,41.12 6.99,42.39 12.7,42.39 13.97,43.66 13.97,50.01 12.7,51.28 J2.3
TXD
  Bottom 0.406: IC2.14 41.91,20.8 39.37,18.26 39.37,13.18 38.1,11.91 20.32,11.91 17.78,14.45 6.99,14.45 4.45,16.99 4.45,41.76 6.35,43.66 12.06,43.66 12.7,44.3 12.7,47.47 11.63,48.54
  Bottom 0.61: 11.63,48.54 J2.2
VCC
  Bottom 0.406: 83.82,95.1 R2.1 | 69.85,42.39 69.85,32.87 69.98,32.87 70.1,32.74 69.85,32.49 C1.1 | 36.83,37.31 36.83,41.76 37.47,42.39
  Bottom 0.508: U$3.32 39.37,43.66 54.61,43.66 55.88,42.39 U$6.32 | U$3.30 40.64,47.47 41.91,48.74 57.15,48.74 58.42,47.47 U$6.30
  Bottom 0.61: U$5.30 32.3,47.47 31.03,46.2 31.03,43.66 32.3,42.39 U$5.32 | 36.83,37.31 39.37,37.31 | R1.1 28.31,90.28 27.94,90.65 | U$8.P$1 77.47,20.8 69.85,28.42 C1.1
  Bottom 0.813: U$5.30 U$3.30 | U$5.32 37.47,42.39 U$3.32 | U$6.32 69.85,42.39 U$4.32 | U$6.30 U$4.30 | 39.37,37.31 43.18,33.5 C10.2 IC2.16 45.72,25.88 48.26,28.42 C4.2 | C2.1 46.99,33.5 43.18,37.31 36.83,37.31
  Bottom 1.27: X1.+5V X1.+5V@1 147.32,89.38 141.6,95.1 83.82,95.1 73.03,95.1 68.58,90.65 | 68.58,90.65 U$1.P$2 | 68.58,90.65 27.94,90.65 20.93,90.65 17.12,86.84 17.12,69.09 21.59,64.62 21.59,60.17 19.05,57.63 19.05,43.66 17.14,41.76 17.14,36.04 17.12,36.04 18.39,34.77 34.29,34.77 36.83,37.31
WAIT
  Bottom 0.406: X1.WAIT 153.67,66.52 152.4,65.25 152.4,58.9 151.13,57.63 130.81,57.63 116.84,43.66 U$1.P$60
WR
  Bottom 0.61: X1.WR 114.3,36.04 111.76,38.58 U$1.P$58

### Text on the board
Bottom: ECB-VGA | Version 2 | A.Diehl 01/2007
